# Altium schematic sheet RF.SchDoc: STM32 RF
size A4; Date: Not used; ApprovedBy: Not used; CheckedBy: Not used; Author: Not used; CompanyName: STMicroelectronics; DrawnBy: Not used; Engineer: Not used; Organization: Not used; Address1: Not used; Address2: Not used; Address3: Not used; Address4: Not used; DocumentNumber: Not used; Revision: Not used; SheetNumber: 5; SheetTotal: 5
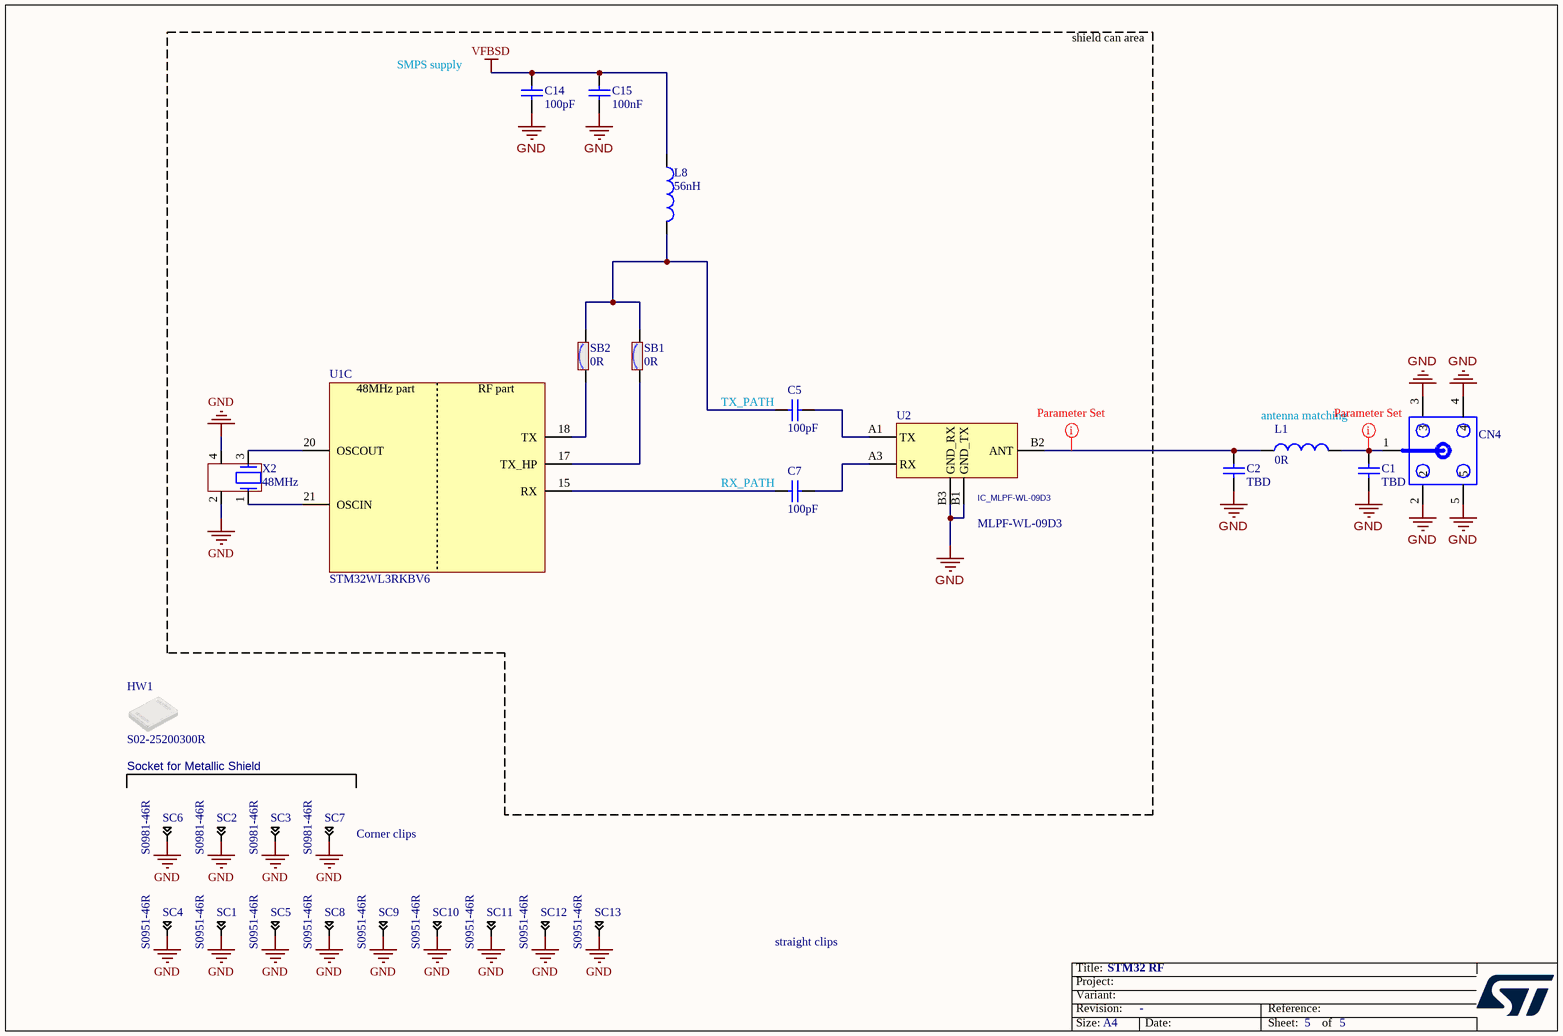
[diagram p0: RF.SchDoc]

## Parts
C1  value TBD  [GRM155--GJM155-0_05-MFG]  (hidden comment: Capacitor)
C2  value TBD  [GRM155--GJM155-0_05-MFG]  (hidden comment: Capacitor)
C5  value 100pF  [C0402]  (hidden comment: Capacitor)
C7  value 100pF  [C0402]  (hidden comment: Capacitor)
C14  value 100pF  [C0402_MURATA_GJM-GRM15_H0P5]  (hidden comment: Capacitor)
C15  value 100nF  [C0402_MURATA_GJM-GRM15_H0P5]  (hidden comment: Capacitor)
CN4  142-0701-851  [142-0701-851]  (value not drawn)
HW1  value S02-25200300R  [SHIELD_HARWIN_S02-25200300_15X20_H3]  (hidden comment: S02-20150300)
L1  value 0R  [L0402]  (hidden comment: Inductor)
L8  value 56nH  [IND_0402_MURATA_LQW15AN_H0P5]  (hidden comment: Inductor)
SB1  value 0R  [SOLDER-BRIDGE_R0201_0R]  (hidden comment: SB_ON)
SB2  value 0R  [SOLDER-BRIDGE_R0201_0R]  (hidden comment: SB_ON)
SC1  value S0951-46R  [CLIP_HARWIN_S0951-46R]  (hidden comment: Shield-clip_S0951-46R)
SC2  value S0981-46R  [CLIP_HARWIN_S0981-46R]  (hidden comment: Shield-clip_S0951-46R)
SC3  value S0981-46R  [CLIP_HARWIN_S0981-46R]  (hidden comment: Shield-clip_S0951-46R)
SC4  value S0951-46R  [CLIP_HARWIN_S0951-46R]  (hidden comment: Shield-clip_S0951-46R)
SC5  value S0951-46R  [CLIP_HARWIN_S0951-46R]  (hidden comment: Shield-clip_S0951-46R)
SC6  value S0981-46R  [CLIP_HARWIN_S0981-46R]  (hidden comment: Shield-clip_S0951-46R)
SC7  value S0981-46R  [CLIP_HARWIN_S0981-46R]  (hidden comment: Shield-clip_S0951-46R)
SC8  value S0951-46R  [CLIP_HARWIN_S0951-46R]  (hidden comment: Shield-clip_S0951-46R)
SC9  value S0951-46R  [CLIP_HARWIN_S0951-46R]  (hidden comment: Shield-clip_S0951-46R)
SC10  value S0951-46R  [CLIP_HARWIN_S0951-46R]  (hidden comment: Shield-clip_S0951-46R)
SC11  value S0951-46R  [CLIP_HARWIN_S0951-46R]  (hidden comment: Shield-clip_S0951-46R)
SC12  value S0951-46R  [CLIP_HARWIN_S0951-46R]  (hidden comment: Shield-clip_S0951-46R)
SC13  value S0951-46R  [CLIP_HARWIN_S0951-46R]  (hidden comment: Shield-clip_S0951-46R)
U1  value STM32WL3RKBV6  [ICC_VFQFPN32-EPAD_5X5_P050]  (hidden comment: IC_STM32WL3R)  (part C of 3)
U2  IC_MLPF-WL-09D3  value MLPF-WL-09D3  [ICC_CSPG5_1P5X1P9_P060]
X2  value 48MHz  [CRY_NX1612SA_4P]  (hidden comment: XTAL_4_PINS)

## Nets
GND: C1.1 C2.1 C14.1 C15.1 CN4.2 CN4.3 CN4.4 CN4.5 SC1.1 SC2.1 SC3.1 SC4.1 SC5.1 SC6.1 SC7.1 SC8.1 SC9.1 SC10.1 SC11.1 SC12.1 SC13.1 U2.B1(GND_TX) U2.B3(GND_RX) X2.2 X2.4
VFBSD: C14.2 C15.2 L8.1
NetC1_2: C1.2 CN4.1 L1.2
NetC2_2: C2.2 L1.1 U2.B2(ANT)
NetC5_1: C5.1 U2.A1(TX)
NetC5_2: C5.2 L8.2 SB1.2 SB2.2
NetC7_1: C7.1 U1.15(RX)
NetC7_2: C7.2 U2.A3(RX)
NetSB1_1: SB1.1 U1.17(TX_HP)
NetSB2_1: SB2.1 U1.18(TX)
NetU1_20: U1.20(OSCOUT) X2.3
NetU1_21: U1.21(OSCIN) X2.1

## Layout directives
net class NC_RF-50R: NetC1_2, NetC2_2

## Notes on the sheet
- shield can area
- SMPS supply
- (near C5) TX_PATH
- antenna matching
- (near C7) RX_PATH
- Socket for Metallic Shield
- (near SC7) Corner clips
- straight clips

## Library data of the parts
C1 = MCD-01600: Capacitor, MLCC; Part_Preference: Recommended; Manufacturer: MURATA; Component_Country_Of_Origin: China; ShowFields: YES; ID: 3700
C2 = MCD-01600: Capacitor, MLCC,; Part_Preference: Recommended; Manufacturer: MURATA; Component_Country_Of_Origin: China; ShowFields: YES; ID: 3700
C5 C7 C14 = MCD-03446: Capacitor, MLCC, 100pF, 50V, C0G/NP0, +/-1%, 0402, T=0.5mm; Part_Preference: Recommended; Manufacturer: MURATA; Manufacturer_Part_Number: GCM1555C1H101FA16; Order_Code_RS: 247-7780; Component_Country_Of_Origin: China, Japan, Philippines, Singapore; ShowFields: YES; ID: 5562
C15 = MCD-03442: Capacitor, MLCC, 100nF, 25V, X7R, +/-10%, 0402, T=0.5mm; Part_Preference: Recommended; Manufacturer: MURATA; Manufacturer_Part_Number: GRM155R71E104KE14; Order_Code_RS: 247-8011; Component_Country_Of_Origin: China, Japan, Philippines, Singapore; ShowFields: YES; ID: 5558
HW1 = MCD-03503: RFI shield CAN, 25x20x3mm; Part_Type: Misc; Part_Preference: Recommended; Manufacturer: HARWIN; Order_Code_RS: 247-9196; Component_Country_Of_Origin: UK°; ShowFields: YES; ID: 5619
L1 = MCD-01937: Resistor, 0R, 0402, +/-5%, 1/16W; Part_Preference: Recommended; Manufacturer: YAGEO; Manufacturer_Part_Number: RC0402JR-070RL; Order_Code_RS: 618-5804; Component_Country_Of_Origin: China; ShowFields: YES; ID: 4037
L8 = MCD-02074: Inductor, 56nH, +/-0.2nH, Itemp=200mA max, 1R17, 0402, T=0.6mm, Qmin=25; Part_Preference: Recommended; Manufacturer: MURATA; Manufacturer_Part_Number: LQW15AN56NG00; Order_Code_RS: 166-9771; Component_Country_Of_Origin: Japan°°; ShowFields: YES; ID: 4174
SB1 SB2 = MCD-03219: Resistor, 0R, 0201, Solder Bridge ON , 1/20W,; Part_Type: Misc; Part_Preference: Recommended; Manufacturer: YAGEO; Manufacturer_Part_Number: RC0201JR-070RL; Order_Code_RS: 198-7623; Component_Country_Of_Origin: China; ShowFields: YES; ID: 5335
SC1 SC4 SC5 SC8 = MCD-01587: shield clip Harwin S0951-46R to fix RF shielded cavity; Part_Type: Misc; Part_Preference: Recommended; Component_Country_Of_Origin: South Korea
SC2 SC3 SC6 SC7 = MCD-02164: shield clip Harwin S0981-46R to fix RF shielded cavity - SMT RFI Shield Clip, Corner (T+R); Part_Type: Misc; Part_Preference: Recommended; Order_Code_RS: 161-3702; Component_Country_Of_Origin: South Korea; ShowFields: YES; ID: 4264
SC9-SC13 = MCD-01587: RFI shield clip mini TIN SMD; Part_Type: Mechanical; Part_Preference: Recommended; Manufacturer: HARWIN; Component_Country_Of_Origin: South Korea; ShowFields: YES; ID: 3687
U1 = MCD-04431: MCU, ARM Cortex-M0 32-bit, 128KB Flash, 16KB SRAM, With Crypto; Part_Type: IC; Part_Preference: Recommended; Manufacturer: STMICROELECTRONICS; ShowFields: YES; ID: 6547
U2 = MCD-05120: IC, 315MHz low pass filter matched to WBA mini board; Part_Preference: Recommended; Manufacturer: STMICROELECTRONICS; ShowFields: YES; ID: 7236
X2 = MCD-03559: Crystal, 48MHz, 8pF, +/-10 ppm, 22R, 1.6x1.2mm; Part_Type: Crystal_Osc; Part_Preference: Recommended; Manufacturer: NDK; Manufacturer_Part_Number: NX1612SA-48.000 MHz-EXS00A-CS12140; ShowFields: YES; ID: 5675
